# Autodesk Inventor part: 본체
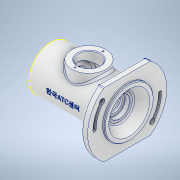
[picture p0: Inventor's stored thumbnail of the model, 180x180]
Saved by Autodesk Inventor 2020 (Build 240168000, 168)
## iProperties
Created: 2022-05
Part Number: 본체
Material: 알루미늄 6061
Document SubType Name: Modeling
Designer: Student
Density: 2.7 g/cm^3
Appearance: 알루미늄 - 평지
Mass: 686.756 g
Surface Area: 622.555 cm^2
Volume: 254.354 cm^3
Author: Student
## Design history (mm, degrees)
sketch "스케치1"
  geometry: L1 (-29.488, 0)-(29.488, 0); L2 (-56, 22.5)-(-48, 22.5); L3 (-45, 22.5)-(-45, 24); L4 (-45, 24)-(-48, 24); L5 (-48, 24)-(-48, 22.5); L6 (-45, 22.5)-(-34, 22.5); L7 (-34, 22.5)-(-34, 17.5); L8 (-34, 17.5)-(-31.75, 17.5); L9 (-31.75, 17.5)-(-31.75, 18.5); L10 (-31.75, 18.5)-(-30, 18.5); L11 (-30, 18.5)-(-30, 17.5); L12 (-30, 17.5)-(-19, 17.5); L13 (-19, 17.5)-(-19, 27); L14 (-19, 27)-(19, 27); L15 (19, 27)-(19, 17.5); L16 (19, 17.5)-(30, 17.5); L17 (30, 17.5)-(30, 15); L18 (30, 15)-(35, 15); L19 (35, 15)-(35, 11); L20 (35, 11)-(37.7, 11); L21 (37.7, 11)-(37.7, 15); L22 (37.7, 15)-(39.647, 15); L23 (59, 30)-(59, 36); L24 (59, 36)-(56, 36); L25 (56, 36)-(56, 58); L26 (56, 58)-(46, 58); L27 (46, 58)-(46, 32); L28 (46, 32)-(37.28, 32); L29 (37.28, 32)-(-56, 32); L30 (-56, 32)-(-56, 22.5); L31 (39.647, 15)-(45, 15); L32 (45, 15)-(45, 20); L33 (45, 20)-(59, 30); 2 further points
  constraints: 66 end point, 24 perpendicular, 4 horizontal, 4 point on line, 1 coincident, 1 midpoint, 1 parallel, 1 vertical
  dimensions: "d2" = 48 diameter of L4 L1; "d3" = 64 diameter of L29 L1; "d4" = 45 diameter of L6 L1; "d5" = 35 diameter of L8 L1; "d6" = 54 diameter of L14 L1; "d8" = 30 diameter of L18 L1; "d9" = 22 diameter of L20 L1; "d10" = 30 diameter of L22 L1; "d11" = 40 diameter of L32.end L1; "d12" = 60 diameter of L23.start L1; "d13" = 72 diameter of L23.end L1; "d14" = 116 diameter of L26 L1; "d18" = 11 distance between parallel lines of L13 L11; "d19" = 38 distance between parallel lines of L15 L13; "d20" = 1.75 distance of L9.end L10.end; "d21" = 4 distance between parallel lines of L11 L7; "d22" = 37 diameter of L10 L1; "d23" = 115 distance between parallel lines of L23 L30; "d24" = 8 distance between parallel lines of L30 L5; "d25" = 45 diameter of L2 L1; "d26" = 3 distance of L3.end L4.end; "d27" = 22 distance between parallel lines of L30 L7; "d28" = 11 distance of L15.end L16.end; "d29" = 5 distance of L17.end L18.end; "d30" = 14 horizontal distance of L32.end L23.start; "d31" = 7.3 distance of L31.end L21.end; "d32" = 56 distance from line of point (0, 0) L30; "d33" = 102 distance between parallel lines of L30 L27; "d34" = 3 distance of L23.end L24.end; "d38" = 19.35308 distance from line of L22.end L23; "d39" = 21.71953 distance from line of L28.end L23; "d40" = 29.51167 distance from line of L1.end L23
revolve "회전1" sketch "스케치1" stored, may be unused: angle "d35" = 90 deg
sketch "스케치2"
  geometry: L1 (-33.985, 47)-(33.985, 47); L2 (-33.985, -47)-(33.985, -47); C1 r 58 at (0, 0) reference; C2 r 36 at (0, 0) reference; A1 r 58 centre (0, 0) between (-33.985, 47) and (33.985, 47) reference; 5 further points
  constraints: 4 end point, 4 point on circle, 1 horizontal, 1 parallel
  dimensions: "d36" = 47 distance from line of L2 point (0, 0); "d37" = 94 distance between parallel lines of L2 L1
extrude "돌출1" cut sketch "스케치2" distance "d41" = 10; taper "d42" = 0 deg
node "작업 평면1"
sketch "스케치7"
  geometry: C1 r 25 at (0, 0); 1 further point
  constraints: 1 centre point, 1 coincident
  dimensions: "d67" = 25 radius of C1
extrude "돌출5" join sketch "스케치7" stored distance "d68" = 38; taper "d69" = 0 deg
sketch "스케치8"
  geometry: C1 r 25 at (0, 0) reference; C2 r 16 at (0, 0); 1 further point
  constraints: 1 centre point, 1 coincident
  dimensions: "d70" = 16 radius of C2
extrude "돌출6" cut sketch "스케치8" stored distance "d71" = 10; taper "d72" = 0 deg
sketch "스케치10"
  geometry: 2 further points
  constraints: 1 vertical alignment
  dimensions: "d80" = 20.5 distance of point (0, 20.5) point (0, 0)
hole "구멍2" sketch "스케치10" at (0, 20.5) diameter "d81" = 2.459; stored, may be unused: countersink angle "d85" = 90 deg, drill point angle "d87" = 118 deg; dims "d82" = 6, "d83" = 4, "d84" = 2, "d86" = 8
node "작업 평면2"
sketch "스케치11"
  geometry: L1 (56, -47)-(56, 47) reference; 2 further points
  constraints: 1 horizontal alignment, 1 other
  dimensions: "d92" = 62 distance from line of L1 point (-6, 0)
feature "엠보싱1" sketch "스케치11" dims "d2" = 48, "d3" = 64, "d4" = 45, "d5" = 35, "d6" = 54, "d8" = 30, "d9" = 22, "d10" = 30, "d11" = 40, "d12" = 60, "d13" = 72, "d14" = 116, "d18" = 11, "d19" = 38, "d20" = 1.75, "d21" = 4, "d22" = 37, "d23" = 115, "d24" = 8, "d25" = 45, "d26" = 3, "d27" = 22, "d28" = 11, "d29" = 5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
fillet "모깎기1" dims "d95" = 3
chamfer "모따기1" distance "d96" = 1; stored, may be unused: second distance "d97" = 2, angle "d98" = 45 deg
fillet "모깎기2" dims "d99" = 0.6
chamfer "모따기2" distance "d100" = 0.7; stored, may be unused: second distance "d101" = 2, angle "d102" = 30 deg
chamfer "모따기3" distance "d103" = 1; stored, may be unused: second distance "d104" = 2, angle "d105" = 30 deg
fillet "모깎기3" dims "d106" = 3
sketch "스케치12"
  geometry: C1 r 32 at (0, 0) reference; C2 r 22.5 at (0, 0) reference; 1 further point
fillet "모깎기4" dims "d107" = 3
fillet "모깎기5" dims "d120" = 3
chamfer "모따기4" distance "d121" = 1; stored, may be unused: second distance "d122" = 2, angle "d123" = 30 deg
chamfer "모따기5" distance "d124" = 1; stored, may be unused: second distance "d125" = 2, angle "d126" = 30 deg
feature "스레드1" dims "d127" = 8, "d128" = 0
sketch "스케치15"
  geometry: L1 (33, -44)-(81, -44); L2 (33, -44)-(69.77, -13.146); L3 (33, -44)-(-15, -44); L4 (33, -44)-(-3.77, -74.854); A1 r 48 centre (33, -44) between (81, -44) and (69.77, -13.146); A2 r 48 centre (33, -44) between (81, -44) and (69.77, -13.146); A3 r 50.25 centre (33, -44) between (83.25, -44) and (73.58, -14.364); A4 r 45.75 centre (33, -44) between (78.75, -44) and (70.033, -17.138); A5 r 2.25 centre (81, -44) between (78.75, -44) and (83.25, -44); A6 r 4 centre (69.77, -13.146) between (70.033, -17.138) and (73.58, -14.364); A7 r 48 centre (33, -44) between (-15, -44) and (-3.77, -74.854); A8 r 4 centre (-3.77, -74.854) between (-4.033, -70.862) and (-7.58, -73.636); A9 r 48 centre (33, -44) between (-15, -44) and (-3.77, -74.854); A10 r 50.25 centre (33, -44) between (-17.25, -44) and (-7.58, -73.636); A11 r 45.75 centre (33, -44) between (-12.75, -44) and (-4.033, -70.862); A12 r 2.25 centre (-15, -44) between (-12.75, -44) and (-17.25, -44); 1 further point
  constraints: 26 point on circle, 12 centre point, 8 end point, 4 tangent, 3 coincident, 2 horizontal, 1 concentric
  dimensions: "d131" = 48 radius of A1; "d132" = 40 deg angle of L1 L2; "d133" = 48 radius of A2; "d134" = 2.25 radius of A5; "d135" = 4 radius of A6; "d136" = 40 deg angle of L3 L4; "d138" = 4 radius of A8; "d142" = 48 radius of A9; "d143" = 2.25 radius of A12
extrude "돌출10" cut sketch "스케치15" distance "d144" = 10; taper "d145" = 0 deg
extrude "돌출11" cut sketch "스케치15" extent not by distance; stored distance "d146" = 4.4; taper "d147" = 0 deg
sketch "스케치16"
  geometry: A1 r 2.25 centre (81, -44) between (78.75, -44) and (83.25, -44) reference; A2 r 50.25 centre (33, -44) between (83.25, -44) and (73.58, -14.364) reference; A3 r 45.75 centre (33, -44) between (78.75, -44) and (70.033, -17.138) reference; A4 r 4 centre (69.77, -13.146) between (73.58, -14.364) and (70.033, -17.138) reference; A5 r 48 centre (33, -44) between (81, -44) and (69.77, -13.146); A6 r 52 centre (33, -44) between (85, -44) and (72.834, -10.575); A7 r 44 centre (33, -44) between (77, -44) and (66.706, -15.717); A8 r 4 centre (81, -44) between (77, -44) and (85, -44); A9 r 4 centre (69.77, -13.146) between (72.834, -10.575) and (66.706, -15.717); 3 further points
  constraints: 10 point on circle, 5 centre point, 4 tangent, 1 coincident, 1 concentric
extrude "돌출12" cut sketch "스케치16" distance "d148" = 4.4; taper "d149" = 0 deg
fillet "모깎기6" dims "d153" = 3
node "솔리드1"
pattern_circular "원형 패턴1" dims angle "d89" = 360 deg
pattern_circular "원형 패턴2" dims angle "d151" = 360 deg
node "투영된 루프1"
feature "A9D066F2-1C7D-4E18-AEED-F7BC21143FA4" dims "d81" = 2.459, "d82" = 6, "d83" = 4, "d84" = 2, "d85" = 90 deg, "d86" = 8, "d87" = 118 deg
other parameters: "d66" = 38, "d91" = 32
